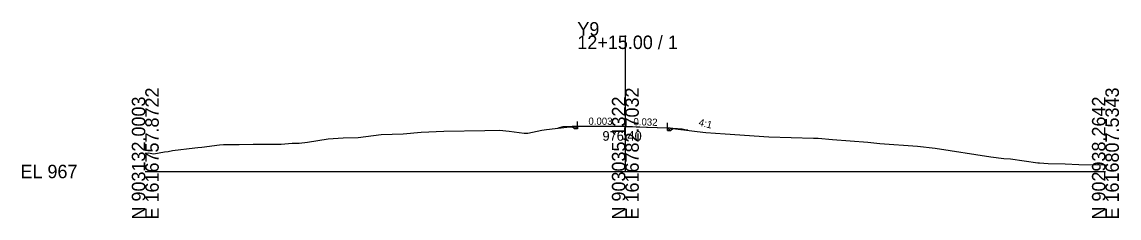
# Model space of a CAD drawing. Extents: x -26 to 1403, y -10 to 3021.
# Drawn here: x 1174.3 to 1402.8, y 490.3 to 531.1 of the extents above; entities that cross this region are included whole.
import ezdxf

# ---------------------------------------------------------------- set-up
doc = ezdxf.new("R2010")
doc.units = 0
for name, color, linetype in [('Exist Cross Section Cell', 7, 'Continuous'), ('Exist XS Center Line Elevation Label', 7, 'Continuous'), ('Exist XS Ground Line', 7, 'Continuous'), ('Prop XS Ditch Slope Text', 7, 'Continuous'), ('Prop XS Earthwork Shape', 7, 'Continuous'), ('Prop XS EOT Tick Mark', 7, 'Continuous'), ('Prop XS Finish Grade', 7, 'Continuous'), ('Prop XS Finish Grade Earthwork', 7, 'Continuous'), ('Prop XS Finish Grade Pavement', 7, 'Continuous'), ('Prop XS Pvmt Edge Slope', 7, 'Continuous'), ('Prop XS SE Text', 7, 'Continuous'), ('Prop XS Subgrade Earthwork', 7, 'Continuous')]:
    doc.layers.add(name, color=color, linetype=linetype)

msp = doc.modelspace()

# ---------------------------------------------------------------- linework, layer by layer
at = {"layer": 'Exist Cross Section Cell'}
for p, q in [((1300, 500), (1300, 528.3)), ((1200, 500), (1300, 500)), ((1300, 500), (1400, 500))]:
    msp.add_line(p, q, dxfattribs=at)
at = {"layer": 'Exist XS Ground Line'}
for p, q in [((1244.37, 507.09), (1249.14, 507.68)), ((1249.14, 507.68), (1253.73, 507.85)), ((1253.73, 507.85), (1257.48, 508.18)), ((1257.48, 508.18), (1262.18, 508.41)), ((1262.18, 508.41), (1270.76, 508.55)), ((1270.76, 508.55), (1273.77, 508.59)), ((1273.77, 508.59), (1275.8, 508.4)), ((1275.8, 508.4), (1278.93, 508)), ((1278.93, 508), (1279.26, 508)), ((1279.26, 508), (1279.68, 507.99)), ((1279.68, 507.99), (1282.57, 508.58)), ((1282.57, 508.58), (1283.59, 508.77)), ((1283.59, 508.77), (1287.78, 509.22)), ((1287.78, 509.22), (1290.01, 509.43)), ((1290.01, 509.43), (1295.18, 509.43)), ((1295.18, 509.43), (1299.91, 509.41)), ((1299.91, 509.41), (1304.6, 509.26)), ((1304.6, 509.26), (1308.8, 509.12)), ((1308.8, 509.12), (1314.98, 508.33)), ((1314.98, 508.33), (1316.79, 508.09)), ((1316.79, 508.09), (1320.81, 507.81)), ((1320.81, 507.81), (1329.86, 507.19)), ((1211.77, 505.05), (1215.45, 505.54)), ((1215.45, 505.54), (1216.29, 505.63)), ((1216.29, 505.63), (1218.77, 505.62)), ((1218.77, 505.62), (1219.53, 505.63)), ((1219.53, 505.63), (1222.49, 505.71)), ((1222.49, 505.71), (1228.29, 505.71)), ((1228.29, 505.71), (1230.58, 505.92)), ((1230.58, 505.92), (1232.05, 505.87)), ((1232.05, 505.87), (1233.8, 506.09)), ((1233.8, 506.09), (1238.06, 506.8)), ((1238.06, 506.8), (1241.23, 507.02)), ((1241.23, 507.02), (1244.37, 507.09)), ((1329.86, 507.19), (1339.16, 506.94)), ((1339.16, 506.94), (1340.18, 506.91)), ((1340.18, 506.91), (1343.15, 506.69)), ((1343.15, 506.69), (1350.51, 506.08)), ((1350.51, 506.08), (1353.04, 505.84)), ((1353.04, 505.84), (1360.83, 505.28)), ((1360.83, 505.28), (1364.51, 504.85)), ((1200, 503.83), (1200.58, 503.86)), ((1200.58, 503.86), (1201.8, 503.68)), ((1201.8, 503.68), (1203.98, 504.08)), ((1203.98, 504.08), (1204.77, 504.16)), ((1204.77, 504.16), (1205.69, 504.35)), ((1205.69, 504.35), (1210.31, 504.91)), ((1210.31, 504.91), (1210.95, 504.98)), ((1210.95, 504.98), (1211.77, 505.05)), ((1364.51, 504.85), (1376.14, 503.03)), ((1376.14, 503.03), (1378.85, 502.74)), ((1378.85, 502.74), (1380.21, 502.64)), ((1380.21, 502.64), (1385.9, 501.83)), ((1385.9, 501.83), (1386.27, 501.81)), ((1386.27, 501.81), (1388.05, 501.7)), ((1388.05, 501.7), (1391.58, 501.6)), ((1391.58, 501.6), (1394.47, 501.49)), ((1394.47, 501.49), (1400, 501.37))]:
    msp.add_line(p, q, dxfattribs=at)
at = {"layer": 'Prop XS Earthwork Shape'}
for points in [[(1288.95, 509.33), (1288.91, 509.38), (1287.01, 509.29), (1285.96, 509.03), (1287.78, 509.22)], [(1290.01, 509.43), (1289.43, 508.86), (1288.95, 509.33)], [(1290.01, 508.85), (1289.43, 508.86), (1290.01, 509.43)], [(1308.8, 509.12), (1309.4, 508.52), (1309.86, 508.98)], [(1308.8, 509.12), (1309.4, 508.52), (1308.8, 508.54)], [(1309.86, 508.98), (1309.91, 509.03), (1311.8, 508.88), (1312.98, 508.59)]]:
    msp.add_lwpolyline(points, close=True, dxfattribs=at)
at = {"layer": 'Prop XS EOT Tick Mark'}
for p, q in [((1290.01, 509.43), (1290.01, 510.43)), ((1308.8, 509.12), (1308.8, 510.12))]:
    msp.add_line(p, q, dxfattribs=at)
at = {"layer": 'Prop XS Finish Grade'}
for p, q in [((1290.01, 509.43), (1288.91, 509.38)), ((1308.8, 509.12), (1309.91, 509.03))]:
    msp.add_line(p, q, dxfattribs=at)
at = {"layer": 'Prop XS Finish Grade Earthwork'}
for p, q in [((1287.01, 509.29), (1285.96, 509.03)), ((1288.91, 509.38), (1287.01, 509.29)), ((1309.91, 509.03), (1311.8, 508.88)), ((1311.8, 508.88), (1312.98, 508.59))]:
    msp.add_line(p, q, dxfattribs=at)
at = {"layer": 'Prop XS Finish Grade Pavement'}
for p, q in [((1290.01, 509.43), (1300, 509.4)), ((1300, 509.4), (1308.8, 509.12))]:
    msp.add_line(p, q, dxfattribs=at)
at = {"layer": 'Prop XS Pvmt Edge Slope'}
for p, q in [((1290.01, 509.43), (1289.43, 508.86)), ((1308.8, 509.12), (1309.4, 508.52))]:
    msp.add_line(p, q, dxfattribs=at)
at = {"layer": 'Prop XS Subgrade Earthwork'}
for p, q in [((1289.43, 508.86), (1288.91, 509.38)), ((1290.01, 508.85), (1289.43, 508.86)), ((1290.01, 508.85), (1290.01, 509.43)), ((1308.8, 508.54), (1308.8, 509.12)), ((1308.8, 508.54), (1309.4, 508.52)), ((1309.4, 508.52), (1309.91, 509.03))]:
    msp.add_line(p, q, dxfattribs=at)

# ---------------------------------------------------------------- texts
at = {"layer": 'Exist Cross Section Cell'}
for s, p in [('Y9', (1290, 528.3)), ('12+15.00 / 1', (1290, 525.5)), ('EL 967', (1174, 498.6))]:
    msp.add_text(s, height=2.8, dxfattribs=at).set_placement(p)
for s, p in [('E 1616757.8722', (1202.8, 490)), ('E 1616782.7032', (1302.8, 490)), ('E 1616807.5343', (1402.8, 490)), ('N 903132.0003', (1200, 490)), ('N 903035.1322', (1300, 490)), ('N 902938.2642', (1400, 490))]:
    msp.add_text(s, height=2.8, rotation=90, dxfattribs=at).set_placement(p)
at = {"layer": 'Exist XS Center Line Elevation Label'}
msp.add_text('976.40', height=2, dxfattribs=at).set_placement((1295.23, 506.4))
at = {"layer": 'Prop XS Ditch Slope Text'}
msp.add_text('4:1', height=1.5, rotation=345.9638, dxfattribs=at).set_placement((1315.16, 509.59))
at = {"layer": 'Prop XS SE Text'}
for s, rotation, p in [('0.003', 359.8362, (1292.3, 509.73)), ('0.032', 358.177, (1301.66, 509.65))]:
    msp.add_text(s, height=1.5, rotation=rotation, dxfattribs=at).set_placement(p)

doc.saveas('drawing.dxf')
